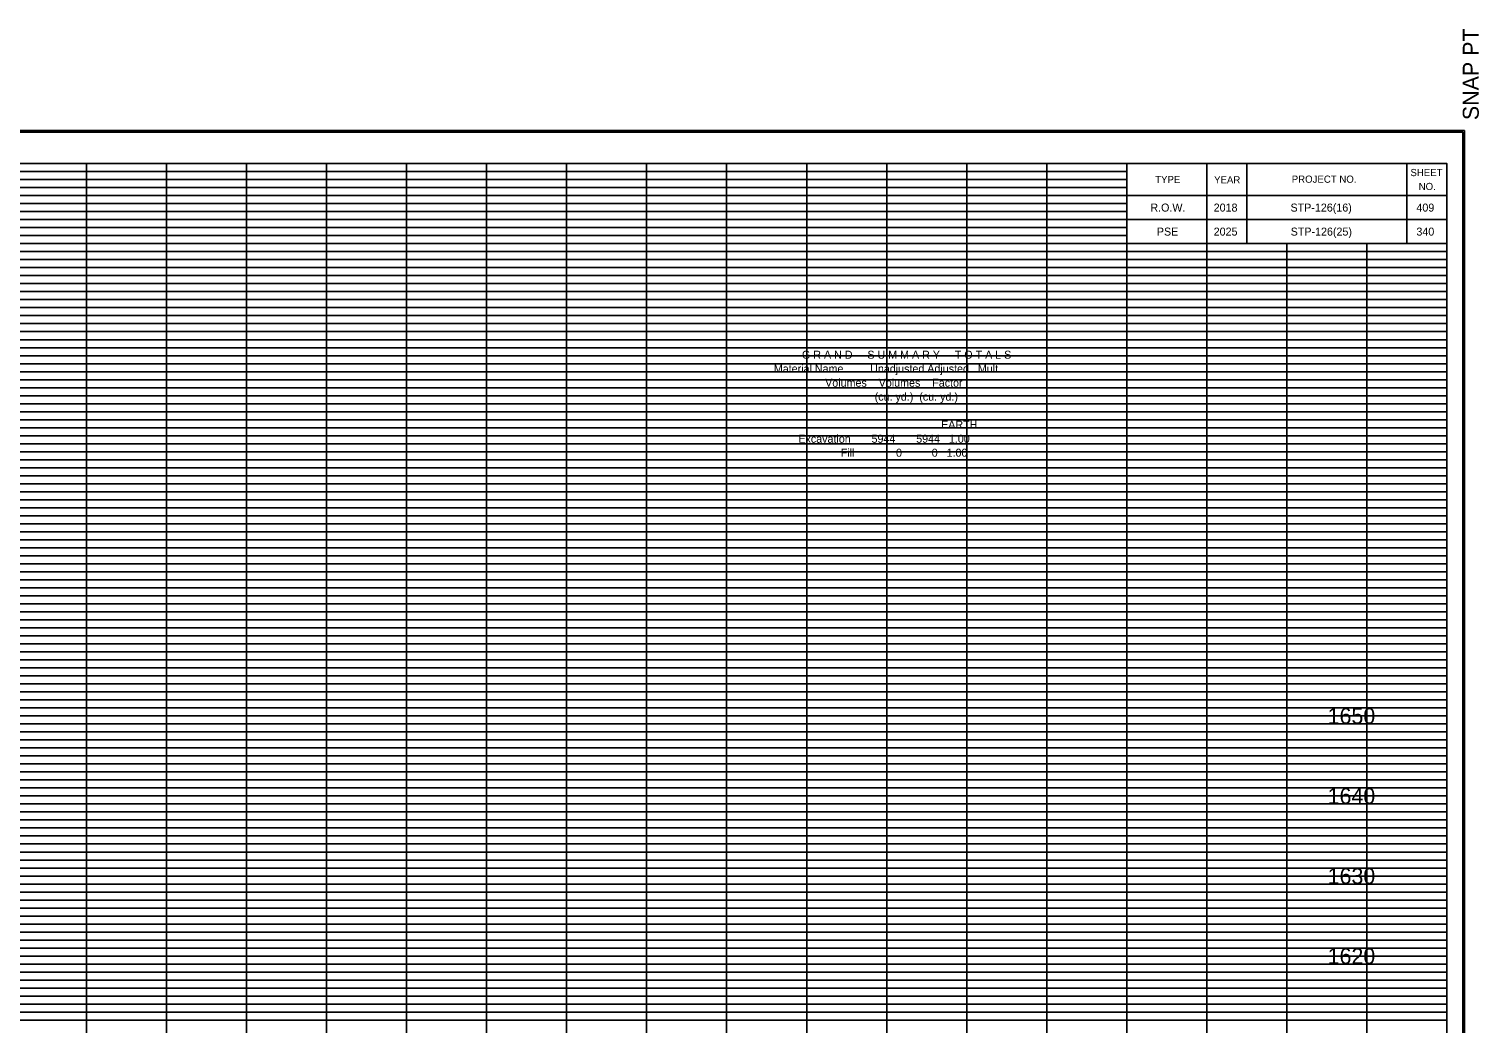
# Model space of a CAD drawing. Extents: x 980 to 1380, y 1248 to 3387.
# Drawn here: x 1142.8 to 1324, y 3262.5 to 3386.8 of the extents above; entities that cross this region are included whole.
import ezdxf

# ---------------------------------------------------------------- set-up
doc = ezdxf.new("R2010")
doc.units = 0
for name, color, linetype in [('DESIGN - SCRATCH - User 1', 7, 'Continuous'), ('DESIGN - SHEET - Corner Text', 7, 'Continuous'), ('DESIGN - SHEET - Light Grid', 7, 'Continuous'), ('DESIGN - SHEET - Linework', 7, 'Continuous'), ('DESIGN - SHEET - Plot Shape', 7, 'Continuous'), ('DESIGN - TYPICAL - Text', 7, 'Continuous')]:
    doc.layers.add(name, color=color, linetype=linetype)

# ---------------------------------------------------------------- blocks, each defined once
blk = doc.blocks.new('XSTSHT')
at = {"layer": 'DESIGN - SCRATCH - User 1'}
for p, q in [((28.5, 20.45), (28.5, 20.45)), ((29.24, 20.45), (29.24, 20.45)), ((30.49, 20.45), (30.49, 20.45)), ((31.74, 20.45), (31.74, 20.45)), ((28.5, 20.15), (28.5, 20.15)), ((29.24, 20.15), (29.24, 20.15)), ((30.49, 20.15), (30.49, 20.15)), ((31.74, 20.15), (31.74, 20.15))]:
    blk.add_line(p, q, dxfattribs=at)
at = {"layer": 'DESIGN - SHEET - Light Grid'}
for p, q in [((8, 20.9), (16, 20.9)), ((16, 20.9), (24, 20.9)), ((24, 20.9), (28, 20.9)), ((8, 20.8), (16, 20.8)), ((8, 20.7), (16, 20.7)), ((16, 20.8), (24, 20.8)), ((16, 20.7), (24, 20.7)), ((24, 20.8), (28, 20.8)), ((24, 20.7), (28, 20.7)), ((8, 20.6), (16, 20.6)), ((8, 20.5), (16, 20.5)), ((16, 20.6), (24, 20.6)), ((16, 20.5), (24, 20.5)), ((24, 20.6), (28, 20.6)), ((24, 20.5), (28, 20.5)), ((8, 20.4), (16, 20.4)), ((8, 20.3), (16, 20.3)), ((16, 20.4), (24, 20.4)), ((16, 20.3), (24, 20.3)), ((24, 20.4), (28, 20.4)), ((24, 20.3), (28, 20.3)), ((8, 20.2), (16, 20.2)), ((16, 20.2), (24, 20.2)), ((24, 20.2), (28, 20.2)), ((8, 20.1), (16, 20.1)), ((16, 20.1), (24, 20.1)), ((24, 20.1), (28, 20.1)), ((8, 19.9), (16, 19.9)), ((8, 19.8), (16, 19.8)), ((16, 19.9), (24, 19.9)), ((16, 19.8), (24, 19.8)), ((24, 19.9), (32, 19.9)), ((24, 19.8), (32, 19.8)), ((8, 19.7), (16, 19.7)), ((8, 19.6), (16, 19.6)), ((16, 19.7), (24, 19.7)), ((16, 19.6), (24, 19.6)), ((24, 19.7), (32, 19.7)), ((24, 19.6), (32, 19.6)), ((8, 19.5), (16, 19.5)), ((8, 19.4), (16, 19.4)), ((16, 19.5), (24, 19.5)), ((16, 19.4), (24, 19.4)), ((24, 19.5), (32, 19.5)), ((24, 19.4), (32, 19.4)), ((8, 19.3), (16, 19.3)), ((16, 19.3), (24, 19.3)), ((24, 19.3), (32, 19.3)), ((8, 19.2), (16, 19.2)), ((8, 19.1), (16, 19.1)), ((16, 19.2), (24, 19.2)), ((16, 19.1), (24, 19.1)), ((24, 19.2), (32, 19.2)), ((24, 19.1), (32, 19.1)), ((8, 18.9), (16, 18.9)), ((16, 18.9), (24, 18.9)), ((24, 18.9), (32, 18.9)), ((8, 18.8), (16, 18.8)), ((8, 18.7), (16, 18.7)), ((16, 18.8), (24, 18.8)), ((16, 18.7), (24, 18.7)), ((24, 18.8), (32, 18.8)), ((24, 18.7), (32, 18.7)), ((8, 18.6), (16, 18.6)), ((8, 18.5), (16, 18.5)), ((16, 18.6), (24, 18.6)), ((16, 18.5), (24, 18.5)), ((24, 18.6), (32, 18.6)), ((24, 18.5), (32, 18.5)), ((8, 18.4), (16, 18.4)), ((8, 18.3), (16, 18.3)), ((16, 18.4), (24, 18.4)), ((16, 18.3), (24, 18.3)), ((24, 18.4), (32, 18.4)), ((24, 18.3), (32, 18.3)), ((8, 18.2), (16, 18.2)), ((16, 18.2), (24, 18.2)), ((24, 18.2), (32, 18.2)), ((8, 18.1), (16, 18.1)), ((16, 18.1), (24, 18.1)), ((24, 18.1), (32, 18.1)), ((8, 17.9), (16, 17.9)), ((8, 17.8), (16, 17.8)), ((16, 17.9), (24, 17.9)), ((16, 17.8), (24, 17.8)), ((24, 17.9), (32, 17.9)), ((24, 17.8), (32, 17.8)), ((8, 17.7), (16, 17.7)), ((8, 17.6), (16, 17.6)), ((16, 17.7), (24, 17.7)), ((16, 17.6), (24, 17.6)), ((24, 17.7), (32, 17.7)), ((24, 17.6), (32, 17.6)), ((8, 17.5), (16, 17.5)), ((8, 17.4), (16, 17.4)), ((16, 17.5), (24, 17.5)), ((16, 17.4), (24, 17.4)), ((24, 17.5), (32, 17.5)), ((24, 17.4), (32, 17.4)), ((8, 17.3), (16, 17.3)), ((16, 17.3), (24, 17.3)), ((24, 17.3), (32, 17.3)), ((8, 17.2), (16, 17.2)), ((8, 17.1), (16, 17.1)), ((16, 17.2), (24, 17.2)), ((16, 17.1), (24, 17.1)), ((24, 17.2), (32, 17.2)), ((24, 17.1), (32, 17.1)), ((8, 16.9), (16, 16.9)), ((16, 16.9), (24, 16.9)), ((24, 16.9), (32, 16.9)), ((8, 16.8), (16, 16.8)), ((8, 16.7), (16, 16.7)), ((16, 16.8), (24, 16.8)), ((16, 16.7), (24, 16.7)), ((24, 16.8), (32, 16.8)), ((24, 16.7), (32, 16.7)), ((8, 16.6), (16, 16.6)), ((8, 16.5), (16, 16.5)), ((16, 16.6), (24, 16.6)), ((16, 16.5), (24, 16.5)), ((24, 16.6), (32, 16.6)), ((24, 16.5), (32, 16.5)), ((8, 16.4), (16, 16.4)), ((16, 16.4), (24, 16.4)), ((24, 16.4), (32, 16.4)), ((8, 16.3), (16, 16.3)), ((8, 16.2), (16, 16.2)), ((16, 16.3), (24, 16.3)), ((16, 16.2), (24, 16.2)), ((24, 16.3), (32, 16.3)), ((24, 16.2), (32, 16.2)), ((8, 16.1), (16, 16.1)), ((16, 16.1), (24, 16.1)), ((24, 16.1), (32, 16.1)), ((8, 15.9), (16, 15.9)), ((8, 15.8), (16, 15.8)), ((16, 15.9), (24, 15.9)), ((16, 15.8), (24, 15.8)), ((24, 15.9), (32, 15.9)), ((24, 15.8), (32, 15.8)), ((8, 15.7), (16, 15.7)), ((8, 15.6), (16, 15.6)), ((16, 15.7), (24, 15.7)), ((16, 15.6), (24, 15.6)), ((24, 15.7), (32, 15.7)), ((24, 15.6), (32, 15.6)), ((8, 15.5), (16, 15.5)), ((8, 15.4), (16, 15.4)), ((16, 15.5), (24, 15.5)), ((16, 15.4), (24, 15.4)), ((24, 15.5), (32, 15.5)), ((24, 15.4), (32, 15.4)), ((8, 15.3), (16, 15.3)), ((16, 15.3), (24, 15.3)), ((24, 15.3), (32, 15.3)), ((8, 15.2), (16, 15.2)), ((8, 15.1), (16, 15.1)), ((16, 15.2), (24, 15.2)), ((16, 15.1), (24, 15.1)), ((24, 15.2), (32, 15.2)), ((24, 15.1), (32, 15.1)), ((8, 14.9), (16, 14.9)), ((16, 14.9), (24, 14.9)), ((24, 14.9), (32, 14.9)), ((8, 14.8), (16, 14.8)), ((8, 14.7), (16, 14.7)), ((16, 14.8), (24, 14.8)), ((16, 14.7), (24, 14.7)), ((24, 14.8), (32, 14.8)), ((24, 14.7), (32, 14.7)), ((8, 14.6), (16, 14.6)), ((8, 14.5), (16, 14.5)), ((16, 14.6), (24, 14.6)), ((16, 14.5), (24, 14.5)), ((24, 14.6), (32, 14.6)), ((24, 14.5), (32, 14.5)), ((8, 14.4), (16, 14.4)), ((16, 14.4), (24, 14.4)), ((24, 14.4), (32, 14.4)), ((8, 14.3), (16, 14.3)), ((8, 14.2), (16, 14.2)), ((16, 14.3), (24, 14.3)), ((16, 14.2), (24, 14.2)), ((24, 14.3), (32, 14.3)), ((24, 14.2), (32, 14.2)), ((8, 14.1), (16, 14.1)), ((16, 14.1), (24, 14.1)), ((24, 14.1), (32, 14.1)), ((8, 13.9), (16, 13.9)), ((8, 13.8), (16, 13.8)), ((16, 13.9), (24, 13.9)), ((16, 13.8), (24, 13.8)), ((24, 13.9), (32, 13.9)), ((24, 13.8), (32, 13.8)), ((8, 13.7), (16, 13.7)), ((8, 13.6), (16, 13.6)), ((16, 13.7), (24, 13.7)), ((16, 13.6), (24, 13.6)), ((24, 13.7), (32, 13.7)), ((24, 13.6), (32, 13.6)), ((8, 13.5), (16, 13.5)), ((16, 13.5), (24, 13.5)), ((24, 13.5), (32, 13.5)), ((8, 13.4), (16, 13.4)), ((8, 13.3), (16, 13.3)), ((16, 13.4), (24, 13.4)), ((16, 13.3), (24, 13.3)), ((24, 13.4), (32, 13.4)), ((24, 13.3), (32, 13.3)), ((8, 13.2), (16, 13.2)), ((8, 13.1), (16, 13.1)), ((16, 13.2), (24, 13.2)), ((16, 13.1), (24, 13.1)), ((24, 13.2), (32, 13.2)), ((24, 13.1), (32, 13.1)), ((8, 12.9), (16, 12.9)), ((16, 12.9), (24, 12.9)), ((24, 12.9), (32, 12.9)), ((8, 12.8), (16, 12.8)), ((8, 12.7), (16, 12.7)), ((16, 12.8), (24, 12.8)), ((16, 12.7), (24, 12.7)), ((24, 12.8), (32, 12.8)), ((24, 12.7), (32, 12.7)), ((8, 12.6), (16, 12.6)), ((16, 12.6), (24, 12.6)), ((24, 12.6), (32, 12.6)), ((8, 12.5), (16, 12.5)), ((8, 12.4), (16, 12.4)), ((16, 12.5), (24, 12.5)), ((16, 12.4), (24, 12.4)), ((24, 12.5), (32, 12.5)), ((24, 12.4), (32, 12.4)), ((8, 12.3), (16, 12.3)), ((8, 12.2), (16, 12.2)), ((16, 12.3), (24, 12.3)), ((16, 12.2), (24, 12.2)), ((24, 12.3), (32, 12.3)), ((24, 12.2), (32, 12.2)), ((8, 12.1), (16, 12.1)), ((16, 12.1), (24, 12.1)), ((24, 12.1), (32, 12.1)), ((8, 11.9), (16, 11.9)), ((8, 11.8), (16, 11.8)), ((16, 11.9), (24, 11.9)), ((16, 11.8), (24, 11.8)), ((24, 11.9), (32, 11.9)), ((24, 11.8), (32, 11.8)), ((8, 11.7), (16, 11.7)), ((8, 11.6), (16, 11.6)), ((16, 11.7), (24, 11.7)), ((16, 11.6), (24, 11.6)), ((24, 11.7), (32, 11.7)), ((24, 11.6), (32, 11.6)), ((8, 11.5), (16, 11.5)), ((16, 11.5), (24, 11.5)), ((24, 11.5), (32, 11.5)), ((8, 11.4), (16, 11.4)), ((8, 11.3), (16, 11.3)), ((16, 11.4), (24, 11.4)), ((16, 11.3), (24, 11.3)), ((24, 11.4), (32, 11.4)), ((24, 11.3), (32, 11.3)), ((8, 11.2), (16, 11.2)), ((8, 11.1), (16, 11.1)), ((16, 11.2), (24, 11.2)), ((16, 11.1), (24, 11.1)), ((24, 11.2), (32, 11.2)), ((24, 11.1), (32, 11.1)), ((8, 10.9), (16, 10.9)), ((16, 10.9), (24, 10.9)), ((24, 10.9), (32, 10.9)), ((8, 10.8), (16, 10.8)), ((8, 10.7), (16, 10.7)), ((16, 10.8), (24, 10.8)), ((16, 10.7), (24, 10.7)), ((24, 10.8), (32, 10.8)), ((24, 10.7), (32, 10.7)), ((8, 10.6), (16, 10.6)), ((16, 10.6), (24, 10.6)), ((24, 10.6), (32, 10.6)), ((8, 10.5), (16, 10.5)), ((8, 10.4), (16, 10.4)), ((16, 10.5), (24, 10.5)), ((16, 10.4), (24, 10.4)), ((24, 10.5), (32, 10.5)), ((24, 10.4), (32, 10.4)), ((8, 10.3), (16, 10.3)), ((16, 10.3), (24, 10.3)), ((24, 10.3), (32, 10.3))]:
    blk.add_line(p, q, dxfattribs=at)
at = {"layer": 'DESIGN - SHEET - Linework'}
for p, q in [((-1.823, 21.414), (32.217, 21.414)), ((32.217, 21.414), (32.217, -0.414)), ((15, 0), (15, 21)), ((16, 0), (16, 21)), ((17, 0), (17, 21)), ((18, 0), (18, 21)), ((19, 0), (19, 21)), ((20, 0), (20, 21)), ((21, 0), (21, 21)), ((22, 0), (22, 21)), ((23, 0), (23, 21)), ((24, 0), (24, 21)), ((25, 0), (25, 21)), ((26, 0), (26, 21)), ((27, 0), (27, 21)), ((0, 20), (28, 20)), ((28, 0), (28, 20)), ((29, 0), (29, 20)), ((30, 0), (30, 20)), ((31, 0), (31, 20)), ((0, 19), (32, 19)), ((0, 18), (32, 18)), ((0, 17), (32, 17)), ((0, 16), (32, 16)), ((0, 15), (32, 15)), ((0, 14), (32, 14)), ((0, 13), (32, 13)), ((0, 12), (32, 12)), ((0, 11), (32, 11))]:
    blk.add_line(p, q, dxfattribs=at)
for points in [[(0, 21), (0, 0), (32, 0), (32, 21), (0, 21)], [(28, 21), (28, 20), (32, 20), (32, 21), (31.5, 21), (31.5, 20), (29.5, 20), (29.5, 21), (29, 21), (29, 20), (32, 20), (28, 20), (28, 20.3), (32, 20.3), (32, 20.6), (28, 20.6)]]:
    blk.add_lwpolyline(points, dxfattribs=at)
at = {"layer": 'DESIGN - SHEET - Plot Shape'}
for points in [[(-1.803, 21.394), (32.197, 21.394), (32.197, -0.394), (-1.803, -0.394)], [(-0.85, 21), (32, 21), (32, -0.25), (-0.85, -0.25)]]:
    blk.add_lwpolyline(points, close=True, dxfattribs=at)
at = {"layer": 'DESIGN - SHEET - Corner Text'}
blk.add_text('  SNAP PT', height=0.2, rotation=90, dxfattribs=at).set_placement((32.397, 21.394))
for s, p in [('TYPE', (28.354, 20.756)), ('YEAR', (29.09, 20.752)), ('PROJECT NO.', (30.06, 20.76)), ('SHEET', (31.543, 20.843)), ('NO.', (31.646, 20.669))]:
    blk.add_text(s, height=0.09, dxfattribs=at).set_placement(p)

msp = doc.modelspace()

# ---------------------------------------------------------------- linework, layer by layer
at = {"layer": 'DESIGN - SHEET - Plot Shape'}
msp.add_lwpolyline([(991.5, 3157.5), (1320, 3157.5), (1320, 3370), (991.5, 3370)], close=True, dxfattribs=at)

# ---------------------------------------------------------------- block references
at = {"layer": 'DESIGN - TYPICAL - Text', "xscale": 10, "yscale": 10}
msp.add_blockref('XSTSHT', (1000, 3160), dxfattribs=at)

# ---------------------------------------------------------------- texts
at = {"layer": 'DESIGN - SHEET - Corner Text'}
for s, p in [('R.O.W.', (1282.94, 3364)), ('2018', (1290.85, 3364)), ('STP-126(16)', (1300.45, 3364)), ('409', (1316.18, 3364)), ('PSE', (1283.75, 3361)), ('2025', (1290.85, 3361)), ('STP-126(25)', (1300.47, 3361)), ('340', (1316.18, 3361))]:
    msp.add_text(s, height=1, dxfattribs=at).set_placement(p)
at = {"layer": 'DESIGN - TYPICAL - Text'}
for s, height, p in [('G R A N D     S U M M A R Y     T O T A L S', 1, (1239.41, 3345.62)), ('               Material Name         Unadjusted Adjusted   Mult', 1, (1230.32, 3343.88)), ('                                     Volumes    Volumes    Factor', 1, (1228.56, 3342.12)), ('                                     (cu. yd.)  (cu. yd.)', 1, (1234.75, 3340.38)), ('        ---------------------------- ---------- ---------- ------', 1, (1232.85, 3338.62)), ('        EARTH', 1, (1253.82, 3336.88)), ('                          Excavation       5944       5944   1.00', 1, (1229.3, 3335.12)), ('                            Fill              0          0   1.00', 1, (1233.85, 3333.38)), ('     1650     ', 2, (1301.37, 3300)), ('     1640     ', 2, (1301.37, 3290)), ('     1630     ', 2, (1301.37, 3280)), ('     1620     ', 2, (1301.37, 3270))]:
    msp.add_text(s, height=height, dxfattribs=at).set_placement(p)

doc.saveas('drawing.dxf')
